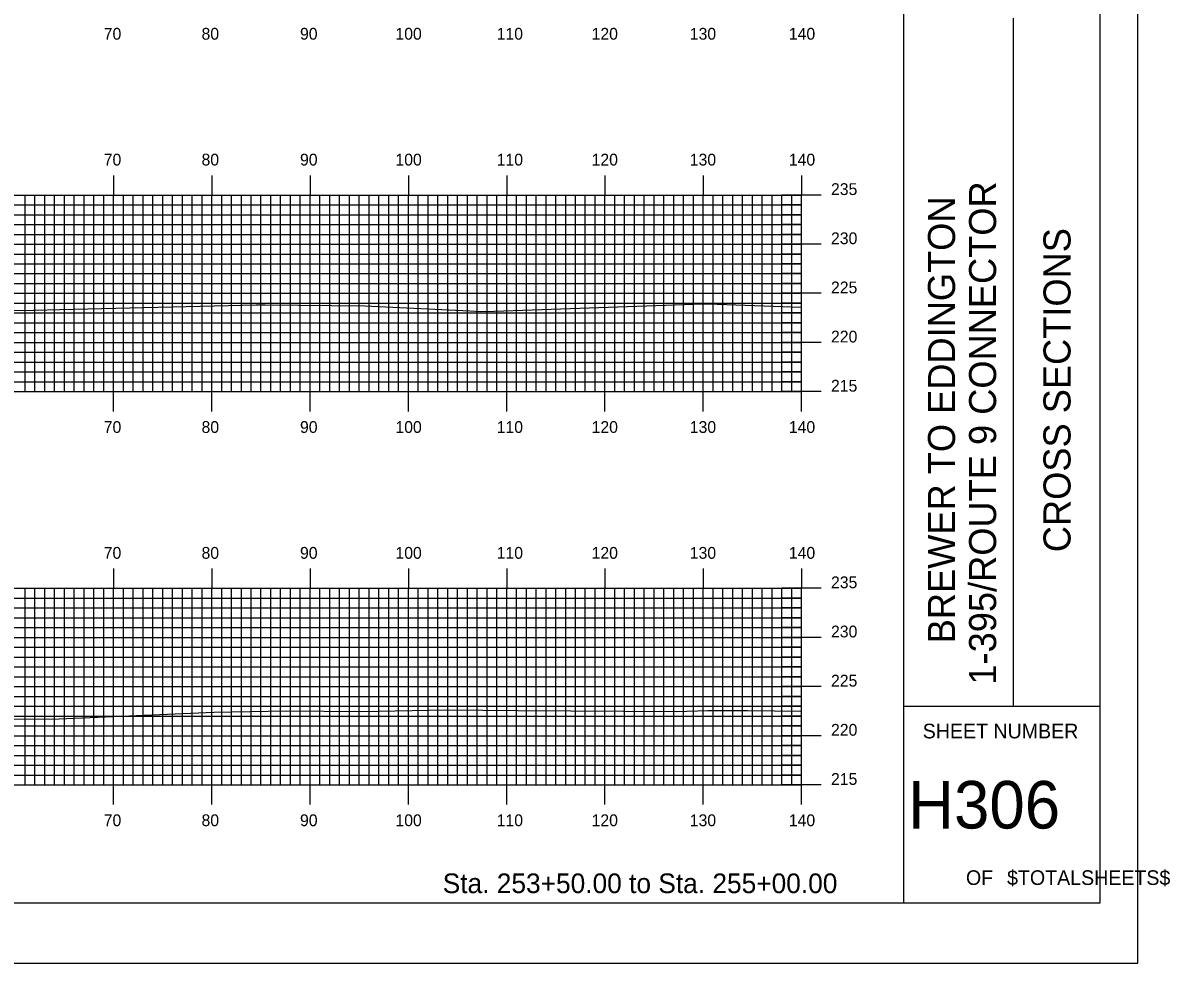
# Model space of a CAD drawing. Extents: x 1804684 to 1805027, y 442591 to 442811.
# Drawn here: x 1804910.5 to 1805027.2, y 442590.5 to 442686.2 of the extents above; entities that cross this region are included whole.
import ezdxf

# ---------------------------------------------------------------- set-up
doc = ezdxf.new("R2010")
doc.units = 0
for name, color, linetype in [('BORDER', 7, 'Continuous'), ('H_V ANNOTATION', 7, 'Continuous'), ('MAJOR', 7, 'Continuous'), ('MINOR', 7, 'Continuous'), ('PLOT BOUNDARY', 7, 'Continuous'), ('S_Roadway_Centerline', 7, 'Continuous')]:
    doc.layers.add(name, color=color, linetype=linetype)

msp = doc.modelspace()

# ---------------------------------------------------------------- linework, layer by layer
at = {"layer": 'BORDER'}
for p, q in [((1805000.08, 442596.67), (1805000.08, 442806.67)), ((1805011.26, 442616.67), (1805011.26, 442686.67)), ((1805000.08, 442616.67), (1805020.08, 442616.67))]:
    msp.add_line(p, q, dxfattribs=at)
msp.add_lwpolyline([(1804700.08, 442596.67), (1805020.08, 442596.67), (1805020.08, 442806.67), (1804700.08, 442806.67)], close=True, dxfattribs=at)
at = {"layer": 'MAJOR'}
for p, q in [((1804919.68, 442670.67), (1804919.68, 442668.67)), ((1804929.68, 442670.67), (1804929.68, 442668.67)), ((1804939.68, 442670.67), (1804939.68, 442668.67)), ((1804949.68, 442670.67), (1804949.68, 442668.67)), ((1804959.68, 442670.67), (1804959.68, 442668.67)), ((1804969.68, 442670.67), (1804969.68, 442668.67)), ((1804979.68, 442670.67), (1804979.68, 442668.67)), ((1804989.68, 442670.67), (1804989.68, 442668.67)), ((1804709.68, 442668.67), (1804989.68, 442668.67)), ((1804709.68, 442668.67), (1804989.68, 442668.67)), ((1804919.68, 442648.67), (1804919.68, 442668.67)), ((1804929.68, 442648.67), (1804929.68, 442668.67)), ((1804939.68, 442648.67), (1804939.68, 442668.67)), ((1804949.68, 442648.67), (1804949.68, 442668.67)), ((1804959.68, 442648.67), (1804959.68, 442668.67)), ((1804969.68, 442648.67), (1804969.68, 442668.67)), ((1804979.68, 442648.67), (1804979.68, 442668.67)), ((1804991.68, 442668.67), (1804987.68, 442668.67)), ((1804989.68, 442648.67), (1804989.68, 442668.67)), ((1804989.68, 442648.67), (1804989.68, 442668.67)), ((1804709.68, 442663.67), (1804989.68, 442663.67)), ((1804991.68, 442663.67), (1804987.68, 442663.67)), ((1804709.68, 442658.67), (1804989.68, 442658.67)), ((1804991.68, 442658.67), (1804987.68, 442658.67)), ((1804709.68, 442653.67), (1804989.68, 442653.67)), ((1804991.68, 442653.67), (1804987.68, 442653.67)), ((1804709.68, 442648.67), (1804989.68, 442648.67)), ((1804709.68, 442648.67), (1804989.68, 442648.67)), ((1804919.68, 442646.66), (1804919.68, 442648.67)), ((1804929.68, 442646.66), (1804929.68, 442648.67)), ((1804939.68, 442646.66), (1804939.68, 442648.67)), ((1804949.68, 442646.66), (1804949.68, 442648.67)), ((1804959.68, 442646.66), (1804959.68, 442648.67)), ((1804969.68, 442646.66), (1804969.68, 442648.67)), ((1804979.68, 442646.66), (1804979.68, 442648.67)), ((1804991.68, 442648.67), (1804987.68, 442648.67)), ((1804989.68, 442646.66), (1804989.68, 442648.67)), ((1804919.68, 442630.67), (1804919.68, 442628.67)), ((1804929.68, 442630.67), (1804929.68, 442628.67)), ((1804939.68, 442630.67), (1804939.68, 442628.67)), ((1804949.68, 442630.67), (1804949.68, 442628.67)), ((1804959.68, 442630.67), (1804959.68, 442628.67)), ((1804969.68, 442630.67), (1804969.68, 442628.67)), ((1804979.68, 442630.67), (1804979.68, 442628.67)), ((1804989.68, 442630.67), (1804989.68, 442628.67)), ((1804709.68, 442628.67), (1804989.68, 442628.67)), ((1804709.68, 442628.67), (1804989.68, 442628.67)), ((1804919.68, 442608.67), (1804919.68, 442628.67)), ((1804929.68, 442608.67), (1804929.68, 442628.67)), ((1804939.68, 442608.67), (1804939.68, 442628.67)), ((1804949.68, 442608.67), (1804949.68, 442628.67)), ((1804959.68, 442608.67), (1804959.68, 442628.67)), ((1804969.68, 442608.67), (1804969.68, 442628.67)), ((1804979.68, 442608.67), (1804979.68, 442628.67)), ((1804991.68, 442628.67), (1804987.68, 442628.67)), ((1804989.68, 442608.67), (1804989.68, 442628.67)), ((1804989.68, 442608.67), (1804989.68, 442628.67)), ((1804709.68, 442623.67), (1804989.68, 442623.67)), ((1804991.68, 442623.67), (1804987.68, 442623.67)), ((1804709.68, 442618.67), (1804989.68, 442618.67)), ((1804991.68, 442618.67), (1804987.68, 442618.67)), ((1804709.68, 442613.67), (1804989.68, 442613.67)), ((1804991.68, 442613.67), (1804987.68, 442613.67)), ((1804709.68, 442608.67), (1804989.68, 442608.67)), ((1804709.68, 442608.67), (1804989.68, 442608.67)), ((1804919.68, 442606.66), (1804919.68, 442608.67)), ((1804929.68, 442606.66), (1804929.68, 442608.67)), ((1804939.68, 442606.66), (1804939.68, 442608.67)), ((1804949.68, 442606.66), (1804949.68, 442608.67)), ((1804959.68, 442606.66), (1804959.68, 442608.67)), ((1804969.68, 442606.66), (1804969.68, 442608.67)), ((1804979.68, 442606.66), (1804979.68, 442608.67)), ((1804991.68, 442608.67), (1804987.68, 442608.67)), ((1804989.68, 442606.66), (1804989.68, 442608.67))]:
    msp.add_line(p, q, dxfattribs=at)
at = {"layer": 'MINOR'}
for p, q in [((1804709.68, 442667.67), (1804989.68, 442667.67)), ((1804910.68, 442648.67), (1804910.68, 442668.67)), ((1804911.68, 442648.67), (1804911.68, 442668.67)), ((1804912.68, 442648.67), (1804912.68, 442668.67)), ((1804913.68, 442648.67), (1804913.68, 442668.67)), ((1804914.68, 442648.67), (1804914.68, 442668.67)), ((1804915.68, 442648.67), (1804915.68, 442668.67)), ((1804916.68, 442648.67), (1804916.68, 442668.67)), ((1804917.68, 442648.67), (1804917.68, 442668.67)), ((1804918.68, 442648.67), (1804918.68, 442668.67)), ((1804920.68, 442648.67), (1804920.68, 442668.67)), ((1804921.68, 442648.67), (1804921.68, 442668.67)), ((1804922.68, 442648.67), (1804922.68, 442668.67)), ((1804923.68, 442648.67), (1804923.68, 442668.67)), ((1804924.68, 442648.67), (1804924.68, 442668.67)), ((1804925.68, 442648.67), (1804925.68, 442668.67)), ((1804926.68, 442648.67), (1804926.68, 442668.67)), ((1804927.68, 442648.67), (1804927.68, 442668.67)), ((1804928.68, 442648.67), (1804928.68, 442668.67)), ((1804930.68, 442648.67), (1804930.68, 442668.67)), ((1804931.68, 442648.67), (1804931.68, 442668.67)), ((1804932.68, 442648.67), (1804932.68, 442668.67)), ((1804933.68, 442648.67), (1804933.68, 442668.67)), ((1804934.68, 442648.67), (1804934.68, 442668.67)), ((1804935.68, 442648.67), (1804935.68, 442668.67)), ((1804936.68, 442648.67), (1804936.68, 442668.67)), ((1804937.68, 442648.67), (1804937.68, 442668.67)), ((1804938.68, 442648.67), (1804938.68, 442668.67)), ((1804940.68, 442648.67), (1804940.68, 442668.67)), ((1804941.68, 442648.67), (1804941.68, 442668.67)), ((1804942.68, 442648.67), (1804942.68, 442668.67)), ((1804943.68, 442648.67), (1804943.68, 442668.67)), ((1804944.68, 442648.67), (1804944.68, 442668.67)), ((1804945.68, 442648.67), (1804945.68, 442668.67)), ((1804946.68, 442648.67), (1804946.68, 442668.67)), ((1804947.68, 442648.67), (1804947.68, 442668.67)), ((1804948.68, 442648.67), (1804948.68, 442668.67)), ((1804950.68, 442648.67), (1804950.68, 442668.67)), ((1804951.68, 442648.67), (1804951.68, 442668.67)), ((1804952.68, 442648.67), (1804952.68, 442668.67)), ((1804953.68, 442648.67), (1804953.68, 442668.67)), ((1804954.68, 442648.67), (1804954.68, 442668.67)), ((1804955.68, 442648.67), (1804955.68, 442668.67)), ((1804956.68, 442648.67), (1804956.68, 442668.67)), ((1804957.68, 442648.67), (1804957.68, 442668.67)), ((1804958.68, 442648.67), (1804958.68, 442668.67)), ((1804960.68, 442648.67), (1804960.68, 442668.67)), ((1804961.68, 442648.67), (1804961.68, 442668.67)), ((1804962.68, 442648.67), (1804962.68, 442668.67)), ((1804963.68, 442648.67), (1804963.68, 442668.67)), ((1804964.68, 442648.67), (1804964.68, 442668.67)), ((1804965.68, 442648.67), (1804965.68, 442668.67)), ((1804966.68, 442648.67), (1804966.68, 442668.67)), ((1804967.68, 442648.67), (1804967.68, 442668.67)), ((1804968.68, 442648.67), (1804968.68, 442668.67)), ((1804970.68, 442648.67), (1804970.68, 442668.67)), ((1804971.68, 442648.67), (1804971.68, 442668.67)), ((1804972.68, 442648.67), (1804972.68, 442668.67)), ((1804973.68, 442648.67), (1804973.68, 442668.67)), ((1804974.68, 442648.67), (1804974.68, 442668.67)), ((1804975.68, 442648.67), (1804975.68, 442668.67)), ((1804976.68, 442648.67), (1804976.68, 442668.67)), ((1804977.68, 442648.67), (1804977.68, 442668.67)), ((1804978.68, 442648.67), (1804978.68, 442668.67)), ((1804980.68, 442648.67), (1804980.68, 442668.67)), ((1804981.68, 442648.67), (1804981.68, 442668.67)), ((1804982.68, 442648.67), (1804982.68, 442668.67)), ((1804983.68, 442648.67), (1804983.68, 442668.67)), ((1804984.68, 442648.67), (1804984.68, 442668.67)), ((1804985.68, 442648.67), (1804985.68, 442668.67)), ((1804986.68, 442648.67), (1804986.68, 442668.67)), ((1804987.68, 442648.67), (1804987.68, 442668.67)), ((1804989.68, 442667.67), (1804987.68, 442667.67)), ((1804988.68, 442648.67), (1804988.68, 442668.67)), ((1804709.68, 442666.67), (1804989.68, 442666.67)), ((1804989.68, 442666.67), (1804987.68, 442666.67)), ((1804709.68, 442665.67), (1804989.68, 442665.67)), ((1804989.68, 442665.67), (1804987.68, 442665.67)), ((1804709.68, 442664.67), (1804989.68, 442664.67)), ((1804989.68, 442664.67), (1804987.68, 442664.67)), ((1804709.68, 442662.67), (1804989.68, 442662.67)), ((1804989.68, 442662.67), (1804987.68, 442662.67)), ((1804709.68, 442661.67), (1804989.68, 442661.67)), ((1804709.68, 442660.67), (1804989.68, 442660.67)), ((1804989.68, 442661.67), (1804987.68, 442661.67)), ((1804989.68, 442660.67), (1804987.68, 442660.67)), ((1804709.68, 442659.67), (1804989.68, 442659.67)), ((1804989.68, 442659.67), (1804987.68, 442659.67)), ((1804709.68, 442657.67), (1804989.68, 442657.67)), ((1804989.68, 442657.67), (1804987.68, 442657.67)), ((1804709.68, 442656.67), (1804989.68, 442656.67)), ((1804989.68, 442656.67), (1804987.68, 442656.67)), ((1804709.68, 442655.67), (1804989.68, 442655.67)), ((1804989.68, 442655.67), (1804987.68, 442655.67)), ((1804709.68, 442654.67), (1804989.68, 442654.67)), ((1804989.68, 442654.67), (1804987.68, 442654.67)), ((1804709.68, 442652.67), (1804989.68, 442652.67)), ((1804989.68, 442652.67), (1804987.68, 442652.67)), ((1804709.68, 442651.67), (1804989.68, 442651.67)), ((1804989.68, 442651.67), (1804987.68, 442651.67)), ((1804709.68, 442650.67), (1804989.68, 442650.67)), ((1804989.68, 442650.67), (1804987.68, 442650.67)), ((1804709.68, 442649.67), (1804989.68, 442649.67)), ((1804989.68, 442649.67), (1804987.68, 442649.67)), ((1804910.68, 442608.67), (1804910.68, 442628.67)), ((1804911.68, 442608.67), (1804911.68, 442628.67)), ((1804912.68, 442608.67), (1804912.68, 442628.67)), ((1804913.68, 442608.67), (1804913.68, 442628.67)), ((1804914.68, 442608.67), (1804914.68, 442628.67)), ((1804915.68, 442608.67), (1804915.68, 442628.67)), ((1804916.68, 442608.67), (1804916.68, 442628.67)), ((1804917.68, 442608.67), (1804917.68, 442628.67)), ((1804918.68, 442608.67), (1804918.68, 442628.67)), ((1804920.68, 442608.67), (1804920.68, 442628.67)), ((1804921.68, 442608.67), (1804921.68, 442628.67)), ((1804922.68, 442608.67), (1804922.68, 442628.67)), ((1804923.68, 442608.67), (1804923.68, 442628.67)), ((1804924.68, 442608.67), (1804924.68, 442628.67)), ((1804925.68, 442608.67), (1804925.68, 442628.67)), ((1804926.68, 442608.67), (1804926.68, 442628.67)), ((1804927.68, 442608.67), (1804927.68, 442628.67)), ((1804928.68, 442608.67), (1804928.68, 442628.67)), ((1804930.68, 442608.67), (1804930.68, 442628.67)), ((1804931.68, 442608.67), (1804931.68, 442628.67)), ((1804932.68, 442608.67), (1804932.68, 442628.67)), ((1804933.68, 442608.67), (1804933.68, 442628.67)), ((1804934.68, 442608.67), (1804934.68, 442628.67)), ((1804935.68, 442608.67), (1804935.68, 442628.67)), ((1804936.68, 442608.67), (1804936.68, 442628.67)), ((1804937.68, 442608.67), (1804937.68, 442628.67)), ((1804938.68, 442608.67), (1804938.68, 442628.67)), ((1804940.68, 442608.67), (1804940.68, 442628.67)), ((1804941.68, 442608.67), (1804941.68, 442628.67)), ((1804942.68, 442608.67), (1804942.68, 442628.67)), ((1804943.68, 442608.67), (1804943.68, 442628.67)), ((1804944.68, 442608.67), (1804944.68, 442628.67)), ((1804945.68, 442608.67), (1804945.68, 442628.67)), ((1804946.68, 442608.67), (1804946.68, 442628.67)), ((1804947.68, 442608.67), (1804947.68, 442628.67)), ((1804948.68, 442608.67), (1804948.68, 442628.67)), ((1804950.68, 442608.67), (1804950.68, 442628.67)), ((1804951.68, 442608.67), (1804951.68, 442628.67)), ((1804952.68, 442608.67), (1804952.68, 442628.67)), ((1804953.68, 442608.67), (1804953.68, 442628.67)), ((1804954.68, 442608.67), (1804954.68, 442628.67)), ((1804955.68, 442608.67), (1804955.68, 442628.67)), ((1804956.68, 442608.67), (1804956.68, 442628.67)), ((1804957.68, 442608.67), (1804957.68, 442628.67)), ((1804958.68, 442608.67), (1804958.68, 442628.67)), ((1804960.68, 442608.67), (1804960.68, 442628.67)), ((1804961.68, 442608.67), (1804961.68, 442628.67)), ((1804962.68, 442608.67), (1804962.68, 442628.67)), ((1804963.68, 442608.67), (1804963.68, 442628.67)), ((1804964.68, 442608.67), (1804964.68, 442628.67)), ((1804965.68, 442608.67), (1804965.68, 442628.67)), ((1804966.68, 442608.67), (1804966.68, 442628.67)), ((1804967.68, 442608.67), (1804967.68, 442628.67)), ((1804968.68, 442608.67), (1804968.68, 442628.67)), ((1804970.68, 442608.67), (1804970.68, 442628.67)), ((1804971.68, 442608.67), (1804971.68, 442628.67)), ((1804972.68, 442608.67), (1804972.68, 442628.67)), ((1804973.68, 442608.67), (1804973.68, 442628.67)), ((1804974.68, 442608.67), (1804974.68, 442628.67)), ((1804975.68, 442608.67), (1804975.68, 442628.67)), ((1804976.68, 442608.67), (1804976.68, 442628.67)), ((1804977.68, 442608.67), (1804977.68, 442628.67)), ((1804978.68, 442608.67), (1804978.68, 442628.67)), ((1804980.68, 442608.67), (1804980.68, 442628.67)), ((1804981.68, 442608.67), (1804981.68, 442628.67)), ((1804982.68, 442608.67), (1804982.68, 442628.67)), ((1804983.68, 442608.67), (1804983.68, 442628.67)), ((1804984.68, 442608.67), (1804984.68, 442628.67)), ((1804985.68, 442608.67), (1804985.68, 442628.67)), ((1804986.68, 442608.67), (1804986.68, 442628.67)), ((1804987.68, 442608.67), (1804987.68, 442628.67)), ((1804988.68, 442608.67), (1804988.68, 442628.67)), ((1804709.68, 442627.67), (1804989.68, 442627.67)), ((1804989.68, 442627.67), (1804987.68, 442627.67)), ((1804709.68, 442626.67), (1804989.68, 442626.67)), ((1804709.68, 442625.67), (1804989.68, 442625.67)), ((1804989.68, 442626.67), (1804987.68, 442626.67)), ((1804989.68, 442625.67), (1804987.68, 442625.67)), ((1804709.68, 442624.67), (1804989.68, 442624.67)), ((1804989.68, 442624.67), (1804987.68, 442624.67)), ((1804709.68, 442622.67), (1804989.68, 442622.67)), ((1804989.68, 442622.67), (1804987.68, 442622.67)), ((1804709.68, 442621.67), (1804989.68, 442621.67)), ((1804989.68, 442621.67), (1804987.68, 442621.67)), ((1804709.68, 442620.67), (1804989.68, 442620.67)), ((1804989.68, 442620.67), (1804987.68, 442620.67)), ((1804709.68, 442619.67), (1804989.68, 442619.67)), ((1804989.68, 442619.67), (1804987.68, 442619.67)), ((1804709.68, 442617.67), (1804989.68, 442617.67)), ((1804989.68, 442617.67), (1804987.68, 442617.67)), ((1804709.68, 442616.67), (1804989.68, 442616.67)), ((1804989.68, 442616.67), (1804987.68, 442616.67)), ((1804709.68, 442615.67), (1804989.68, 442615.67)), ((1804989.68, 442615.67), (1804987.68, 442615.67)), ((1804709.68, 442614.67), (1804989.68, 442614.67)), ((1804989.68, 442614.67), (1804987.68, 442614.67)), ((1804709.68, 442612.67), (1804989.68, 442612.67)), ((1804709.68, 442611.67), (1804989.68, 442611.67)), ((1804989.68, 442612.67), (1804987.68, 442612.67)), ((1804989.68, 442611.67), (1804987.68, 442611.67)), ((1804709.68, 442610.67), (1804989.68, 442610.67)), ((1804989.68, 442610.67), (1804987.68, 442610.67)), ((1804709.68, 442609.67), (1804989.68, 442609.67)), ((1804989.68, 442609.67), (1804987.68, 442609.67))]:
    msp.add_line(p, q, dxfattribs=at)
at = {"layer": 'PLOT BOUNDARY'}
msp.add_lwpolyline([(1804683.89, 442590.55), (1805023.89, 442590.55), (1805023.89, 442810.55), (1804683.89, 442810.55)], close=True, dxfattribs=at)
at = {"layer": 'S_Roadway_Centerline'}
for points in [[(1804895.71, 442656.94), (1804911.53, 442656.95), (1804911.68, 442656.95), (1804914.22, 442657.02), (1804934.19, 442657.5), (1804935.1, 442657.51), (1804945.26, 442657.41), (1804955.94, 442656.88), (1804957.06, 442656.81), (1804958.4, 442656.84), (1804979.7, 442657.59), (1804981.09, 442657.58), (1804989.68, 442657.27)], [(1804908.7, 442615.36), (1804914.14, 442615.38), (1804929.88, 442616.07), (1804937.24, 442616.21), (1804944.95, 442616.12), (1804953.46, 442616.3), (1804957.26, 442616.26), (1804960.81, 442616.22), (1804976.97, 442616.14), (1804980.14, 442616.25), (1804984.19, 442616.24), (1804989.68, 442616.18)]]:
    msp.add_lwpolyline(points, dxfattribs=at)

# ---------------------------------------------------------------- texts
at = {"layer": 'BORDER'}
for s, p in [('1-395/ROUTE 9 CONNECTOR', (1805009.48, 442618.87)), ('BREWER TO EDDINGTON', (1805005.3, 442623.07)), ('CROSS SECTIONS', (1805017.05, 442632.34))]:
    msp.add_text(s, height=2.7557, rotation=90, dxfattribs=at).set_placement(p)
for s, height, p in [('SHEET NUMBER', 1.4905, (1805002.01, 442613.4)), ('H306', 4.839, (1805000.52, 442604.23)), ('OF', 1.491, (1805006.41, 442598.49)), ('$TOTALSHEETS$', 1.4905, (1805010.59, 442598.49))]:
    msp.add_text(s, height=height, dxfattribs=at).set_placement(p)
at = {"layer": 'H_V ANNOTATION'}
for s, height, p in [('70', 1.2, (1804918.68, 442684.47)), ('80', 1.2, (1804928.63, 442684.47)), ('90', 1.2, (1804938.65, 442684.47)), ('100', 1.2, (1804948.36, 442684.47)), ('110', 1.2, (1804958.66, 442684.47)), ('120', 1.2, (1804968.32, 442684.47)), ('130', 1.2, (1804978.31, 442684.47)), ('140', 1.2, (1804988.39, 442684.47)), ('70', 1.2, (1804918.68, 442671.67)), ('80', 1.2, (1804928.63, 442671.67)), ('90', 1.2, (1804938.65, 442671.67)), ('100', 1.2, (1804948.36, 442671.67)), ('110', 1.2, (1804958.66, 442671.67)), ('120', 1.2, (1804968.32, 442671.67)), ('130', 1.2, (1804978.31, 442671.67)), ('140', 1.2, (1804988.39, 442671.67)), ('235', 1.2, (1804992.68, 442668.67)), ('230', 1.2, (1804992.68, 442663.67)), ('225', 1.2, (1804992.68, 442658.67)), ('220', 1.2, (1804992.68, 442653.67)), ('215', 1.2, (1804992.68, 442648.67)), ('70', 1.2, (1804918.68, 442644.47)), ('80', 1.2, (1804928.63, 442644.47)), ('90', 1.2, (1804938.65, 442644.47)), ('100', 1.2, (1804948.36, 442644.47)), ('110', 1.2, (1804958.66, 442644.47)), ('120', 1.2, (1804968.32, 442644.47)), ('130', 1.2, (1804978.31, 442644.47)), ('140', 1.2, (1804988.39, 442644.47)), ('70', 1.2, (1804918.68, 442631.67)), ('80', 1.2, (1804928.63, 442631.67)), ('90', 1.2, (1804938.65, 442631.67)), ('100', 1.2, (1804948.36, 442631.67)), ('110', 1.2, (1804958.66, 442631.67)), ('120', 1.2, (1804968.32, 442631.67)), ('130', 1.2, (1804978.31, 442631.67)), ('140', 1.2, (1804988.39, 442631.67)), ('235', 1.2, (1804992.68, 442628.67)), ('230', 1.2, (1804992.68, 442623.67)), ('225', 1.2, (1804992.68, 442618.67)), ('220', 1.2, (1804992.68, 442613.67)), ('215', 1.2, (1804992.68, 442608.67)), ('70', 1.2, (1804918.68, 442604.47)), ('80', 1.2, (1804928.63, 442604.47)), ('90', 1.2, (1804938.65, 442604.47)), ('100', 1.2, (1804948.36, 442604.47)), ('110', 1.2, (1804958.66, 442604.47)), ('120', 1.2, (1804968.32, 442604.47)), ('130', 1.2, (1804978.31, 442604.47)), ('140', 1.2, (1804988.39, 442604.47)), ('Sta. 253+50.00 to Sta. 255+00.00', 2.0004, (1804953.17, 442597.66))]:
    msp.add_text(s, height=height, dxfattribs=at).set_placement(p)

doc.saveas('drawing.dxf')
